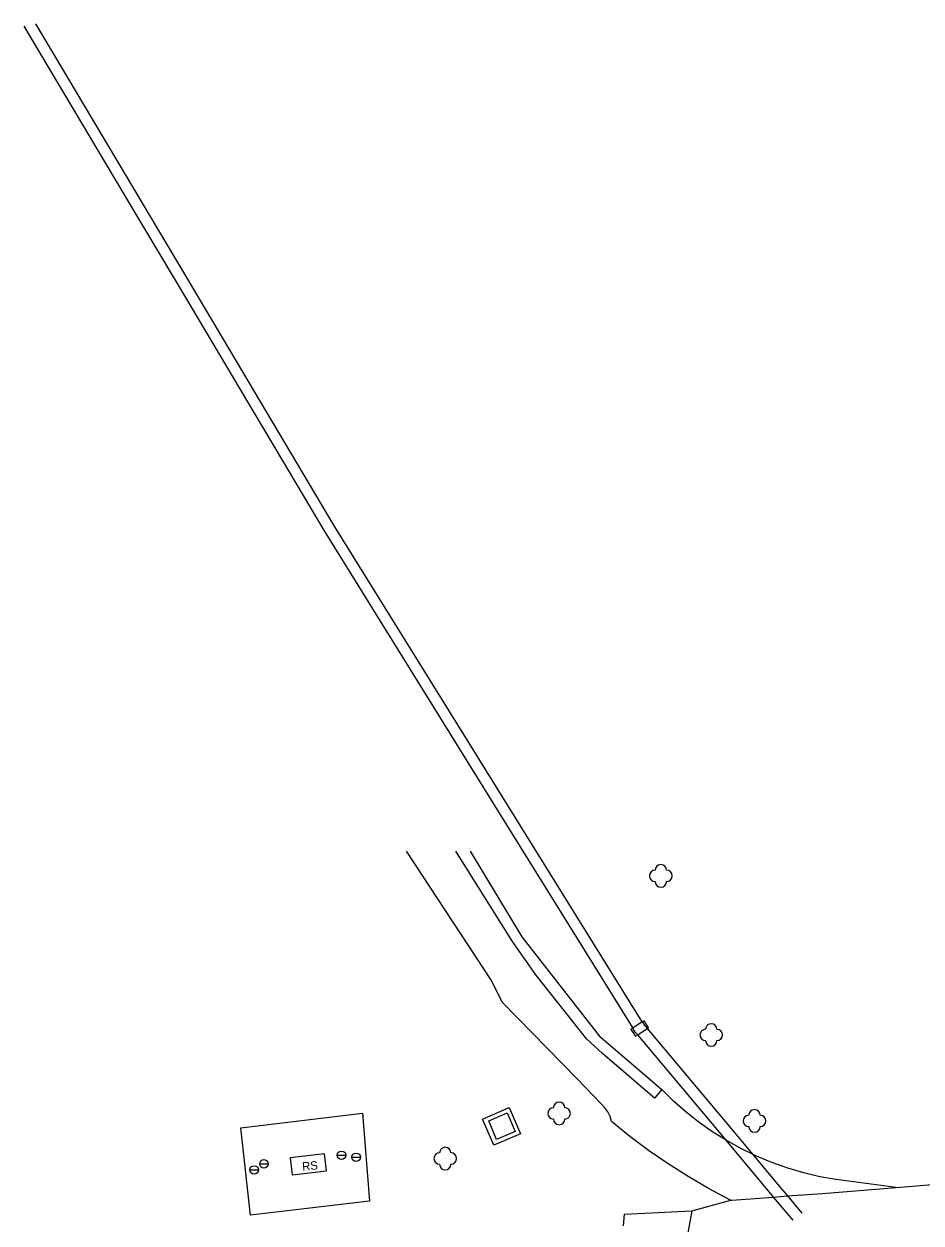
# Model space of a CAD drawing. Extents: x -536391 to -535419, y -1201788 to -1200779.
# Drawn here: x -535812.4 to -535733, y -1201615.3 to -1201509 of the extents above; entities that cross this region are included whole.
import ezdxf

# ---------------------------------------------------------------- set-up
doc = ezdxf.new("R2010")
doc.units = 0
for name, color, linetype in [('BUDOVY_MĚŘ', 7, 'Continuous'), ('POMOC_POPIS', 7, 'Continuous'), ('ROZHRANÍ_PLOCH', 7, 'Continuous'), ('ZELEŇ', 7, 'Continuous'), ('ZN_DOPLŇKOVÉ', 7, 'Continuous')]:
    doc.layers.add(name, color=color, linetype=linetype)

msp = doc.modelspace()

# ---------------------------------------------------------------- linework, layer by layer
at = {"layer": 'BUDOVY_MĚŘ'}
msp.add_lwpolyline([(-535785.81, -1201609.15), (-535788.84, -1201609.5), (-535788.67, -1201611), (-535785.63, -1201610.64), (-535785.81, -1201609.15)], dxfattribs=at)
at = {"layer": 'ROZHRANÍ_PLOCH'}
for points in [[(-535812.44, -1201509.2), (-535802.19, -1201526.43), (-535798.87, -1201532.01), (-535785.84, -1201553.94), (-535773.78, -1201573.37), (-535770.35, -1201578.89), (-535758.48, -1201598.01)], [(-535757.65, -1201597.46), (-535769.5, -1201578.36), (-535772.93, -1201572.84), (-535784.98, -1201553.42), (-535798.01, -1201531.5), (-535801.33, -1201525.92), (-535811.38, -1201509.02)], [(-535749.81, -1201613.26), (-535749.95, -1201613.19), (-535751.8, -1201612.21), (-535753.6, -1201611.15), (-535755.37, -1201610.03), (-535757.09, -1201608.85), (-535758.76, -1201607.6), (-535760.38, -1201606.28), (-535760.5, -1201605.84), (-535760.7, -1201605.43), (-535760.96, -1201605.06), (-535761.28, -1201604.74), (-535763.44, -1201602.48), (-535770.07, -1201595.7), (-535771.01, -1201593.78), (-535778.54, -1201582.31)], [(-535755.93, -1201603.44), (-535756.58, -1201604.2), (-535761.17, -1201600.26), (-535762.56, -1201598.98), (-535767.08, -1201593.27), (-535769.16, -1201590.33), (-535774.16, -1201582.31)], [(-535772.89, -1201582.31), (-535768.32, -1201589.9), (-535761.47, -1201598.68), (-535755.93, -1201603.44)], [(-535757.22, -1201598.04), (-535757.1, -1201597.96), (-535757.5, -1201597.36), (-535757.65, -1201597.46)], [(-535758.48, -1201598.01), (-535758.66, -1201598.13), (-535758.26, -1201598.73), (-535758.06, -1201598.6)], [(-535757.65, -1201597.46), (-535758.48, -1201598.01)], [(-535758.06, -1201598.6), (-535758.27, -1201598.35), (-535758.48, -1201598.01)], [(-535758.06, -1201598.6), (-535757.22, -1201598.04)], [(-535757.65, -1201597.46), (-535757.47, -1201597.75), (-535757.22, -1201598.04)], [(-535757.22, -1201598.04), (-535749.52, -1201607.23), (-535747.89, -1201609.17)], [(-535750.23, -1201607.94), (-535758.06, -1201598.6)], [(-535750.23, -1201607.94), (-535751.4, -1201607.21), (-535752.61, -1201606.36), (-535753.77, -1201605.45), (-535754.88, -1201604.47), (-535755.93, -1201603.44)], [(-535769.62, -1201605.52), (-535768.93, -1201607.17), (-535770.57, -1201607.87), (-535771.26, -1201606.21), (-535769.62, -1201605.52)], [(-535747.89, -1201609.17), (-535748.85, -1201608.71), (-535750.23, -1201607.94)], [(-535746.02, -1201612.97), (-535746.11, -1201612.86), (-535750.23, -1201607.94)], [(-535735.17, -1201612.12), (-535740.46, -1201611.43), (-535741.92, -1201611.17), (-535743.35, -1201610.83), (-535744.77, -1201610.41), (-535746.16, -1201609.92), (-535747.52, -1201609.35), (-535747.89, -1201609.17)], [(-535747.89, -1201609.17), (-535745.34, -1201612.21), (-535744.78, -1201612.88)], [(-535744.78, -1201612.88), (-535741.67, -1201612.65), (-535735.17, -1201612.12), (-535716.86, -1201610.62)], [(-535753.27, -1201614.2), (-535749.81, -1201613.26)], [(-535749.81, -1201613.26), (-535749.73, -1201613.24), (-535746.02, -1201612.97)], [(-535746.02, -1201612.97), (-535744.78, -1201612.88)], [(-535744.28, -1201615.03), (-535746.02, -1201612.97)], [(-535744.78, -1201612.88), (-535743.51, -1201614.39)], [(-535759.33, -1201615.52), (-535759.23, -1201614.49), (-535753.27, -1201614.2)], [(-535753.27, -1201614.2), (-535754.38, -1201620.36)]]:
    msp.add_lwpolyline(points, dxfattribs=at)
at = {"layer": 'ZELEŇ'}
for centre in [(-535756.01, -1201584.51), (-535751.54, -1201598.61), (-535765.02, -1201605.56), (-535747.71, -1201606.23), (-535775.11, -1201609.56)]:
    msp.add_circle(centre, 0.0005, dxfattribs=at)
for centre, start, end in [((-535756.01, -1201584.01), 0, 179.99999), ((-535756.51, -1201584.51), 89.99999, 269.99999), ((-535755.51, -1201584.51), 270, 89.99999), ((-535756.01, -1201585.01), 179.99999, 359.99999), ((-535752.04, -1201598.61), 89.99999, 269.99999), ((-535751.54, -1201598.11), 0, 179.99999), ((-535751.04, -1201598.61), 270, 89.99999), ((-535751.54, -1201599.11), 179.99999, 359.99999), ((-535765.02, -1201605.06), 0, 179.99999), ((-535765.52, -1201605.56), 89.99999, 269.99999), ((-535764.52, -1201605.56), 270, 89.99999), ((-535748.21, -1201606.23), 89.99999, 269.99999), ((-535747.71, -1201605.73), 0, 179.99999), ((-535747.21, -1201606.23), 270, 89.99999), ((-535765.02, -1201606.06), 179.99999, 359.99999), ((-535747.71, -1201606.73), 179.99999, 359.99999), ((-535775.61, -1201609.56), 89.99999, 269.99999), ((-535775.11, -1201609.06), 0, 179.99999), ((-535774.61, -1201609.56), 270, 89.99999), ((-535775.11, -1201610.06), 179.99999, 359.99999)]:
    msp.add_arc(centre, 0.5, start, end, dxfattribs=at)
at = {"layer": 'ZN_DOPLŇKOVÉ'}
for p, q in [((-535791.555, -1201610.03), (-535790.805, -1201610.03)), ((-535784.685, -1201609.27), (-535783.935, -1201609.27)), ((-535783.385, -1201609.45), (-535782.635, -1201609.45)), ((-535792.415, -1201610.57), (-535791.665, -1201610.57))]:
    msp.add_line(p, q, dxfattribs=at)
for points in [[(-535792.37, -1201614.57), (-535793.23, -1201606.83), (-535782.45, -1201605.55), (-535781.81, -1201613.35), (-535785.86, -1201613.82), (-535787.35, -1201613.99), (-535792.37, -1201614.57)], [(-535770.81, -1201608.39), (-535771.82, -1201606.08), (-535769.45, -1201605.05), (-535768.43, -1201607.36), (-535770.81, -1201608.39)]]:
    msp.add_lwpolyline(points, dxfattribs=at)
for centre in [(-535784.31, -1201609.27), (-535783.01, -1201609.45), (-535791.18, -1201610.03), (-535792.04, -1201610.57)]:
    msp.add_circle(centre, 0.375, dxfattribs=at)

# ---------------------------------------------------------------- texts
at = {"layer": 'POMOC_POPIS'}
msp.add_text('RS', height=0.75, rotation=4.78001, dxfattribs=at).set_placement((-535787.76, -1201610.64))

doc.saveas('drawing.dxf')
